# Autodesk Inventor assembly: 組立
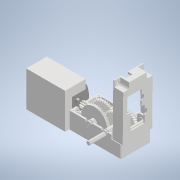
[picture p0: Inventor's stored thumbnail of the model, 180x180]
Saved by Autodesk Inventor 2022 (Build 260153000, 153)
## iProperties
Created: 2024-12
Part Number: 組立
Document SubType Name: Assembly
Designer: jsat7
Author: jsat7
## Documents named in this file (16)
- C:\Users\jsat7\OneDrive\デスクトップ\卒論2024\３DCAD\自在ギヤボックス\組立図\組立.iam
- C:\Users\jsat7\OneDrive\デスクトップ\卒論2024\３DCAD\自在ギヤボックス\部品図\ボックス　下.ipt
- C:\Users\jsat7\OneDrive\デスクトップ\卒論2024\３DCAD\自在ギヤボックス\部品図\B3.ipt
- C:\Users\jsat7\OneDrive\デスクトップ\卒論2024\３DCAD\自在ギヤボックス\部品図\2段平ギア.iam
- C:\Users\jsat7\OneDrive\デスクトップ\卒論2024\３DCAD\自在ギヤボックス\部品図\B4.ipt
- C:\Users\jsat7\OneDrive\デスクトップ\卒論2024\３DCAD\自在ギヤボックス\部品図\B6.ipt
- C:\Users\jsat7\OneDrive\デスクトップ\卒論2024\３DCAD\自在ギヤボックス\部品図\丸棒.ipt
- C:\Users\jsat7\OneDrive\デスクトップ\卒論2024\３DCAD\自在ギヤボックス\部品図\クラウンギア.iam
- C:\Users\jsat7\OneDrive\デスクトップ\卒論2024\３DCAD\自在ギヤボックス\部品図\モーター　ピニオンギア.iam
- C:\Users\jsat7\OneDrive\デスクトップ\卒論2024\３DCAD\自在ギヤボックス\部品図\モーター　箱.ipt
- C:\Users\jsat7\OneDrive\デスクトップ\卒論2024\３DCAD\自在ギヤボックス\部品図\ピニオンギア.ipt
- C:\Users\jsat7\OneDrive\デスクトップ\卒論2024\３DCAD\自在ギヤボックス\部品図\特殊平ギア.ipt
- C:\Users\jsat7\OneDrive\デスクトップ\卒論2024\３DCAD\自在ギヤボックス\部品図\六角シャフト.ipt
- C:\Users\jsat7\OneDrive\デスクトップ\卒論2024\３DCAD\自在ギヤボックス\部品図\固定器具.ipt
- C:\Users\jsat7\OneDrive\デスクトップ\卒論2024\３DCAD\自在ギヤボックス\部品図\B7.ipt
- C:\Users\jsat7\OneDrive\デスクトップ\卒論2024\３DCAD\自在ギヤボックス\部品図\ボックス　上.ipt
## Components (13 placed, 11 different names)
1. B4:1 — メイト:2, フラッシュ:2, メイト:3
2. B6:1 — メイト:1, メイト:28, メイト:29, フラッシュ:13
3. 丸棒:1 — メイト:3, メイト:5, メイト:20, メイト:28
4. クラウンギア:1 [sub-assembly] — メイト:5, メイト:22, 回転:1, 回転:2, メイト:29
5. モーター　ピニオンギア:1 [sub-assembly] — フラッシュ:5, フラッシュ:6, メイト:13, メイト:14, フラッシュ:8
6. 平歯車1:1 — メイト:14, フラッシュ:8, 回転:1, 角度:1
7. 平歯車1:2 — リジッド:1, メイト:23, 回転:4
8. 六角シャフト:1 — リジッド:1, リジッド:2, メイト:21, メイト:26
9. 固定器具:1 — リジッド:2, メイト:27
10. 2段平ギア:1 [sub-assembly] — メイト:20, メイト:22, 回転:3, 回転:4
11. 2段平ギア:2 [sub-assembly] — メイト:21, メイト:23, 回転:2, 回転:3
12. B3:1 — メイト:24, フラッシュ:11
13. B7:1 — メイト:25, フラッシュ:12, メイト:26, メイト:27
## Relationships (30: Mate 16, Flush 7, RelateRotation 4, WeldJoint 2, Angle 1)
- メイト:1 [Mate]: B6:1
- メイト:2 [Mate]: B4:1
- フラッシュ:2 [Flush]: B4:1
- メイト:3 [Mate]: B4:1 ↔ 丸棒:1
- メイト:5 [Mate]: 丸棒:1 ↔ クラウンギア:1
- フラッシュ:5 [Flush]: モーター　ピニオンギア:1
- フラッシュ:6 [Flush]: モーター　ピニオンギア:1
- メイト:13 [Mate]: モーター　ピニオンギア:1
- メイト:14 [Mate]: モーター　ピニオンギア:1 ↔ 平歯車1:1
- フラッシュ:8 [Flush]: モーター　ピニオンギア:1 ↔ 平歯車1:1
- リジッド:1 [WeldJoint]: 平歯車1:2 ↔ 六角シャフト:1
- リジッド:2 [WeldJoint]: 六角シャフト:1 ↔ 固定器具:1
- メイト:20 [Mate]: 丸棒:1 ↔ 2段平ギア:1
- メイト:21 [Mate]: 六角シャフト:1 ↔ 2段平ギア:2
- メイト:22 [Mate]: クラウンギア:1 ↔ 2段平ギア:1
- メイト:23 [Mate]: 平歯車1:2 ↔ 2段平ギア:2
- 回転:1 [RelateRotation]: クラウンギア:1 ↔ 平歯車1:1
- 回転:2 [RelateRotation]: クラウンギア:1 ↔ 2段平ギア:2
- 回転:3 [RelateRotation]: 2段平ギア:1 ↔ 2段平ギア:2
- 回転:4 [RelateRotation]: 平歯車1:2 ↔ 2段平ギア:1
- 角度:1 [Angle]: 平歯車1:1
- メイト:24 [Mate]: B3:1
- フラッシュ:11 [Flush]: B3:1
- メイト:25 [Mate]: B7:1
- フラッシュ:12 [Flush]: B7:1
- メイト:26 [Mate]: 六角シャフト:1 ↔ B7:1
- メイト:27 [Mate]: 固定器具:1 ↔ B7:1
- メイト:28 [Mate]: B6:1 ↔ 丸棒:1
- メイト:29 [Mate]: B6:1 ↔ クラウンギア:1
- フラッシュ:13 [Flush]: B6:1
